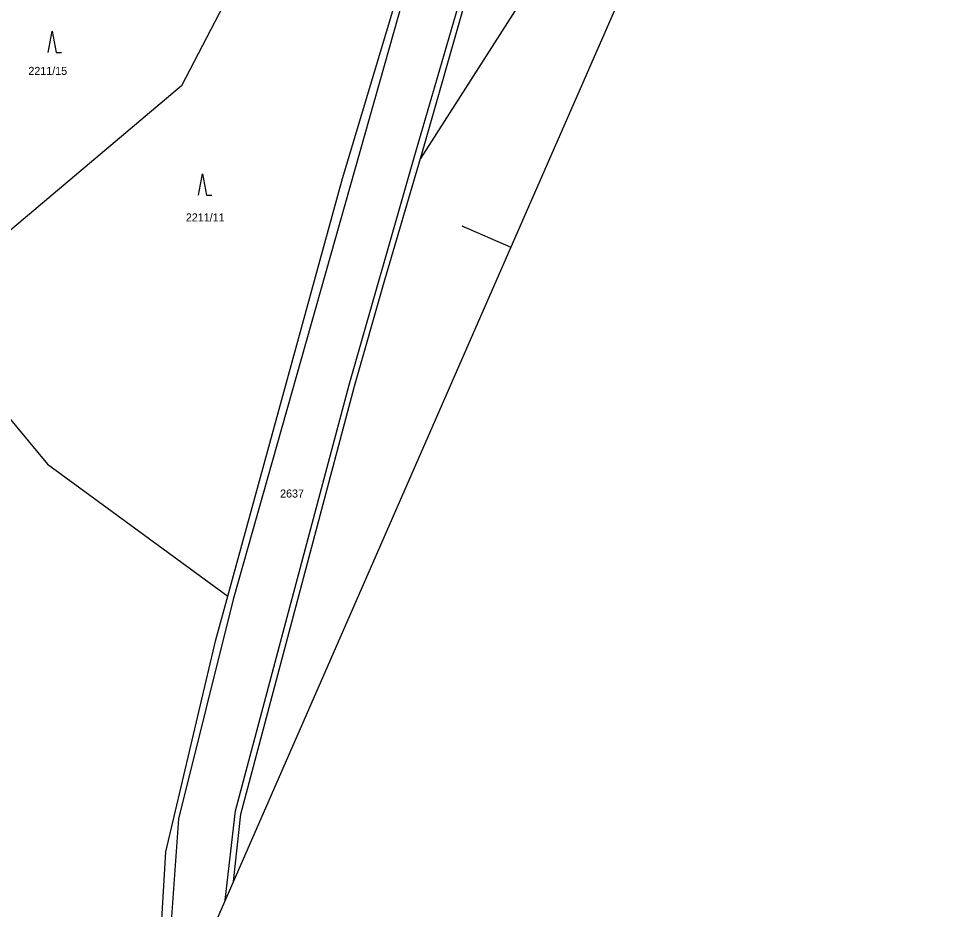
# Model space of a CAD drawing. Extents: x -806856 to -806332, y -1151642 to -1150946.
# Drawn here: x -806508 to -806331.6, y -1151381.6 to -1151214.9 of the extents above; entities that cross this region are included whole.
import ezdxf

# ---------------------------------------------------------------- set-up
doc = ezdxf.new("R2010")
doc.units = 0
for name, color, linetype in [('Default', 7, 'Continuous'), ('formát', 7, 'Continuous'), ('kn_celek - Cisla pozemkovych parcel', 7, 'Continuous'), ('kn_celek - Hranice parcel', 7, 'Continuous'), ('kn_celek - Vnitrni kresby', 7, 'Continuous'), ('kn_celek - Znacky kultur', 7, 'Continuous')]:
    doc.layers.add(name, color=color, linetype=linetype)

# ---------------------------------------------------------------- blocks, each defined once
blk = doc.blocks.new('308')
at = {"layer": 'Default'}
for p, q in [((-7.5, 0.2), (0, 40.2)), ((0, 40.2), (7.5, 0.2)), ((7.5, 0.2), (17.5, 0.2))]:
    blk.add_line(p, q, dxfattribs=at)

msp = doc.modelspace()

# ---------------------------------------------------------------- linework, layer by layer
at = {"layer": 'formát'}
for p, q in [((-806331.63, -1151065.3), (-806415.83, -1151257.68)), ((-806424.99, -1151253.67), (-806415.83, -1151257.68)), ((-806424.99, -1151253.67), (-806415.83, -1151257.68)), ((-806415.83, -1151257.68), (-806500.03, -1151450.06))]:
    msp.add_line(p, q, dxfattribs=at)
at = {"layer": 'kn_celek - Hranice parcel'}
for p, q in [((-806447.38, -1151244.82), (-806426.85, -1151176.65)), ((-806432.32, -1151239.57), (-806414.88, -1151178.55)), ((-806463.36, -1151200.29), (-806477.54, -1151227.46)), ((-806412.88, -1151210.03), (-806432.75, -1151241.03)), ((-806477.54, -1151227.46), (-806526.98, -1151269.12)), ((-806432.75, -1151241.03), (-806432.32, -1151239.57)), ((-806439.41, -1151263.77), (-806432.75, -1151241.03)), ((-806468.83, -1151323), (-806447.38, -1151244.82)), ((-806445.1, -1151283.71), (-806439.41, -1151263.77)), ((-806526.98, -1151269.12), (-806502.64, -1151298.29)), ((-806466.41, -1151363.84), (-806445.1, -1151283.71)), ((-806502.64, -1151298.29), (-806468.83, -1151323)), ((-806471.09, -1151331.22), (-806468.83, -1151323)), ((-806480.46, -1151370.89), (-806471.09, -1151331.22)), ((-806467.8, -1151376.43), (-806466.41, -1151363.84)), ((-806482.78, -1151410.66), (-806480.46, -1151370.89))]:
    msp.add_line(p, q, dxfattribs=at)
at = {"layer": 'kn_celek - Vnitrni kresby'}
for p, q in [((-806433.94, -1151240.84), (-806415.66, -1151178.27)), ((-806434.09, -1151204.41), (-806467.83, -1151323.67)), ((-806446.14, -1151283.47), (-806433.94, -1151240.84)), ((-806467.4, -1151363.22), (-806446.14, -1151283.47)), ((-806467.83, -1151323.67), (-806478.12, -1151364.73)), ((-806469.36, -1151379.98), (-806467.4, -1151363.22)), ((-806478.12, -1151364.73), (-806481.06, -1151406.74))]:
    msp.add_line(p, q, dxfattribs=at)

# ---------------------------------------------------------------- block references
at = {"layer": 'kn_celek - Znacky kultur', "xscale": 0.1, "yscale": 0.10000000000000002}
for p in [(-806501.79, -1151221.24), (-806473.61, -1151247.92)]:
    msp.add_blockref('308', p, dxfattribs=at)

# ---------------------------------------------------------------- texts
at = {"layer": 'kn_celek - Cisla pozemkovych parcel'}
for s, p in [('2211/15', (-806506.22, -1151225.4)), ('2211/11', (-806476.71, -1151252.84)), ('2637', (-806459.05, -1151304.55))]:
    msp.add_text(s, height=1.5, dxfattribs=at).set_placement(p)

doc.saveas('drawing.dxf')
